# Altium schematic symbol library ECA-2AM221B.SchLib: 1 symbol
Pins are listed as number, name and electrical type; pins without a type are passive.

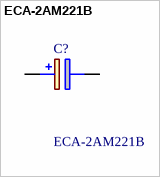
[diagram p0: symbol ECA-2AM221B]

## ECA-2AM221B
designator C?
Aluminum Electrolytic Capacitors - Radial Leaded Al Lytic Cap 85C Radial M Series; Manufacturer_Name: Panasonic; Geometry.Height: 22mm
footprint CAPPRD500W65D1250H2200
pins: 1 +, 2 -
